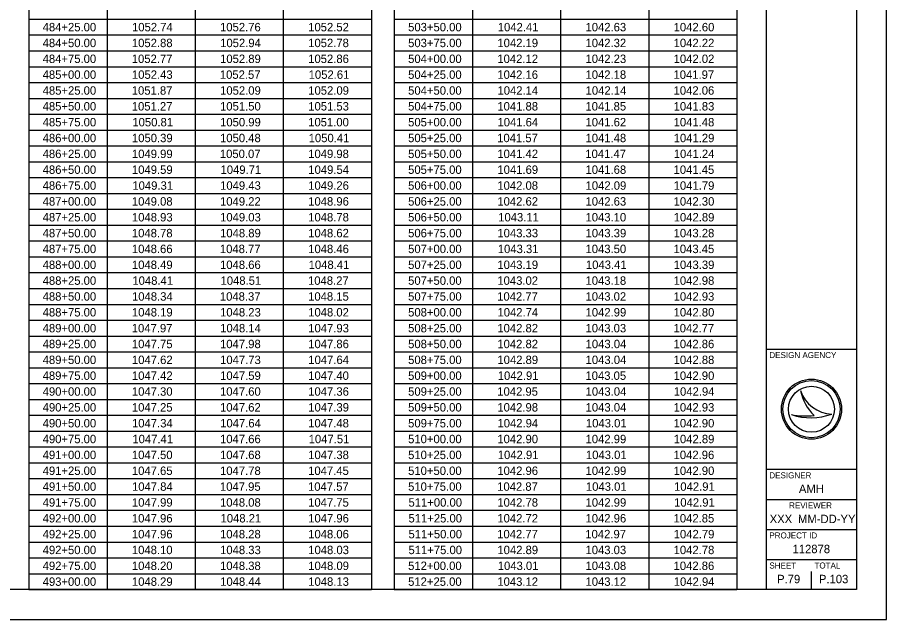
# Model space of a CAD drawing. Extents: x 0 to 34, y 0 to 22.
# Drawn here: x 19.54 to 34, y 0 to 10.02 of the extents above; entities that cross this region are included whole.
import ezdxf

# ---------------------------------------------------------------- set-up
doc = ezdxf.new("R2010")
doc.units = 0
for name, color, linetype in [('SH_Border', 7, 'Continuous'), ('SH_Cut_Line', 7, 'Continuous'), ('SH_Data', 7, 'Continuous'), ('SH_Text', 7, 'Continuous')]:
    doc.layers.add(name, color=color, linetype=linetype)

msp = doc.modelspace()

# ---------------------------------------------------------------- linework, layer by layer
at = {"layer": 'SH_Border'}
for p, q in [((32, 0.5), (32, 21.5)), ((32, 4.5), (33.5, 4.5)), ((32, 2.5), (33.5, 2.5)), ((32, 2), (33.5, 2)), ((32, 1.5), (33.5, 1.5)), ((32, 1), (33.5, 1))]:
    msp.add_line(p, q, dxfattribs=at)
msp.add_lwpolyline([(1.5, 21.5), (33.5, 21.5), (33.5, 0.5), (1.5, 0.5)], close=True, dxfattribs=at)
at = {"layer": 'SH_Cut_Line'}
msp.add_lwpolyline([(0, 0), (34, 0), (34, 22), (0, 22)], close=True, dxfattribs=at)
at = {"layer": 'SH_Data'}
for p, q in [((32.567, 3.81), (32.567, 3.81)), ((32.75, 3.5), (32.75, 3.5)), ((32.417, 3.41), (32.417, 3.41)), ((33.087, 3.419), (33.087, 3.419)), ((32.75, 0.5), (32.75, 0.8)), ((32.375, 0.675), (32.375, 0.675))]:
    msp.add_line(p, q, dxfattribs=at)
for radius in [0.5, 0.477, 0.477, 0.382]:
    msp.add_circle((32.75, 3.5), radius, dxfattribs=at)
for centre, radius, start, end in [((33.116, 3.998), 0.58, 198.9257, 198.9319), ((33.347, 3.97), 0.796, 191.6379, 191.6421), ((33.116, 3.998), 0.58, 198.9319, 267.1657), ((33.347, 3.97), 0.796, 191.6421, 226.0947), ((32.739, 4.37), 1.013, 251.4576, 290.0832), ((32.648, 4.654), 1.266, 259.4964, 259.4995), ((32.739, 4.37), 1.013, 251.4527, 251.4576), ((32.648, 4.654), 1.266, 259.4995, 276.6672)]:
    msp.add_arc(centre, radius, start, end, dxfattribs=at)
at = {"layer": 'SH_Text'}
for p, q in [((19.733, 21.5), (19.733, 0.5)), ((21.034, 21.5), (21.034, 0.5)), ((22.5, 21.5), (22.5, 0.5)), ((23.966, 21.5), (23.966, 0.5)), ((25.432, 21.5), (25.432, 0.5)), ((25.811, 21.5), (25.811, 0.5)), ((27.112, 21.5), (27.112, 0.5)), ((28.578, 21.5), (28.578, 0.5)), ((30.044, 21.5), (30.044, 0.5)), ((31.509, 21.5), (31.509, 0.5)), ((19.733, 9.987), (25.432, 9.987)), ((25.811, 9.987), (31.509, 9.987)), ((19.733, 9.724), (25.432, 9.724)), ((25.811, 9.724), (31.509, 9.724)), ((19.733, 9.46), (25.432, 9.46)), ((25.811, 9.46), (31.509, 9.46)), ((19.733, 9.196), (25.432, 9.196)), ((25.811, 9.196), (31.509, 9.196)), ((19.733, 8.933), (25.432, 8.933)), ((25.811, 8.933), (31.509, 8.933)), ((19.733, 8.669), (25.432, 8.669)), ((25.811, 8.669), (31.509, 8.669)), ((19.733, 8.406), (25.432, 8.406)), ((25.811, 8.406), (31.509, 8.406)), ((19.733, 8.142), (25.432, 8.142)), ((25.811, 8.142), (31.509, 8.142)), ((19.733, 7.879), (25.432, 7.879)), ((25.811, 7.879), (31.509, 7.879)), ((19.733, 7.615), (25.432, 7.615)), ((25.811, 7.615), (31.509, 7.615)), ((19.733, 7.352), (25.432, 7.352)), ((25.811, 7.352), (31.509, 7.352)), ((19.733, 7.088), (25.432, 7.088)), ((25.811, 7.088), (31.509, 7.088)), ((19.733, 6.825), (25.432, 6.825)), ((25.811, 6.825), (31.509, 6.825)), ((19.733, 6.561), (25.432, 6.561)), ((25.811, 6.561), (31.509, 6.561)), ((19.733, 6.298), (25.432, 6.298)), ((25.811, 6.298), (31.509, 6.298)), ((19.733, 6.034), (25.432, 6.034)), ((25.811, 6.034), (31.509, 6.034)), ((19.733, 5.771), (25.432, 5.771)), ((25.811, 5.771), (31.509, 5.771)), ((19.733, 5.507), (25.432, 5.507)), ((25.811, 5.507), (31.509, 5.507)), ((19.733, 5.244), (25.432, 5.244)), ((25.811, 5.244), (31.509, 5.244)), ((19.733, 4.98), (25.432, 4.98)), ((25.811, 4.98), (31.509, 4.98)), ((19.733, 4.716), (25.432, 4.716)), ((25.811, 4.716), (31.509, 4.716)), ((19.733, 4.453), (25.432, 4.453)), ((25.811, 4.453), (31.509, 4.453)), ((19.733, 4.189), (25.432, 4.189)), ((25.811, 4.189), (31.509, 4.189)), ((19.733, 3.926), (25.432, 3.926)), ((25.811, 3.926), (31.509, 3.926)), ((19.733, 3.662), (25.432, 3.662)), ((25.811, 3.662), (31.509, 3.662)), ((19.733, 3.399), (25.432, 3.399)), ((25.811, 3.399), (31.509, 3.399)), ((19.733, 3.135), (25.432, 3.135)), ((25.811, 3.135), (31.509, 3.135)), ((19.733, 2.872), (25.432, 2.872)), ((25.811, 2.872), (31.509, 2.872)), ((19.733, 2.608), (25.432, 2.608)), ((25.811, 2.608), (31.509, 2.608)), ((19.733, 2.345), (25.432, 2.345)), ((25.811, 2.345), (31.509, 2.345)), ((19.733, 2.081), (25.432, 2.081)), ((25.811, 2.081), (31.509, 2.081)), ((19.733, 1.818), (25.432, 1.818)), ((25.811, 1.818), (31.509, 1.818)), ((19.733, 1.554), (25.432, 1.554)), ((25.811, 1.554), (31.509, 1.554)), ((19.733, 1.291), (25.432, 1.291)), ((25.811, 1.291), (31.509, 1.291)), ((19.733, 1.027), (25.432, 1.027)), ((25.811, 1.027), (31.509, 1.027)), ((19.733, 0.764), (25.432, 0.764)), ((25.811, 0.764), (31.509, 0.764)), ((19.733, 0.5), (25.432, 0.5)), ((25.811, 0.5), (31.509, 0.5))]:
    msp.add_line(p, q, dxfattribs=at)

# ---------------------------------------------------------------- texts
at = {"layer": 'SH_Data'}
for s, height, p in [('DESIGN AGENCY', 0.1, (32.05, 4.35)), ('DESIGNER', 0.1, (32.05, 2.35)), ('AMH', 0.14, (32.541, 2.105)), ('REVIEWER', 0.1, (32.378, 1.85)), ('XXX', 0.14, (32.055, 1.605)), ('MM-DD-YY', 0.14, (32.526, 1.605)), ('PROJECT ID', 0.1, (32.05, 1.35)), ('112878', 0.14, (32.435, 1.105)), ('SHEET', 0.1, (32.05, 0.85)), ('TOTAL', 0.1, (32.8, 0.85)), ('P.79', 0.14, (32.178, 0.605)), ('P.103', 0.14, (32.874, 0.605))]:
    msp.add_text(s, height=height, dxfattribs=at).set_placement(p)
at = {"layer": 'SH_Text'}
for s, p in [('484+25.00', (19.964, 9.785)), ('1052.74', (21.45, 9.785)), ('1052.76', (22.914, 9.785)), ('1052.52', (24.38, 9.785)), ('503+50.00', (26.042, 9.785)), ('1042.41', (27.533, 9.785)), ('1042.63', (28.992, 9.785)), ('1042.60', (30.458, 9.785)), ('484+50.00', (19.964, 9.522)), ('1052.88', (21.448, 9.522)), ('1052.94', (22.916, 9.522)), ('1052.78', (24.38, 9.522)), ('503+75.00', (26.042, 9.522)), ('1042.19', (27.527, 9.522)), ('1042.32', (28.992, 9.522)), ('1042.22', (30.458, 9.522)), ('484+75.00', (19.964, 9.258)), ('1052.77', (21.446, 9.258)), ('1052.89', (22.915, 9.258)), ('1052.86', (24.38, 9.258)), ('504+00.00', (26.042, 9.258)), ('1042.12', (27.526, 9.258)), ('1042.23', (28.992, 9.258)), ('1042.02', (30.458, 9.258)), ('485+00.00', (19.964, 8.995)), ('1052.43', (21.449, 8.995)), ('1052.57', (22.911, 8.995)), ('1052.61', (24.388, 8.995)), ('504+25.00', (26.042, 8.995)), ('1042.16', (27.526, 8.995)), ('1042.18', (28.992, 8.995)), ('1041.97', (30.455, 8.995)), ('485+25.00', (19.964, 8.731)), ('1051.87', (21.446, 8.731)), ('1052.09', (22.915, 8.731)), ('1052.09', (24.381, 8.731)), ('504+50.00', (26.042, 8.731)), ('1042.14', (27.528, 8.731)), ('1042.14', (28.994, 8.731)), ('1042.06', (30.457, 8.731)), ('485+50.00', (19.964, 8.468)), ('1051.27', (21.446, 8.468)), ('1051.50', (22.914, 8.468)), ('1051.53', (24.381, 8.468)), ('504+75.00', (26.042, 8.468)), ('1041.88', (27.526, 8.468)), ('1041.85', (28.991, 8.468)), ('1041.83', (30.458, 8.468)), ('485+75.00', (19.964, 8.204)), ('1050.81', (21.456, 8.204)), ('1050.99', (22.915, 8.204)), ('1051.00', (24.38, 8.204)), ('505+00.00', (26.042, 8.204)), ('1041.64', (27.528, 8.204)), ('1041.62', (28.992, 8.204)), ('1041.48', (30.458, 8.204)), ('486+00.00', (19.964, 7.941)), ('1050.39', (21.449, 7.941)), ('1050.48', (22.914, 7.941)), ('1050.41', (24.388, 7.941)), ('505+25.00', (26.042, 7.941)), ('1041.57', (27.523, 7.941)), ('1041.48', (28.992, 7.941)), ('1041.29', (30.459, 7.941)), ('486+25.00', (19.964, 7.677)), ('1049.99', (21.449, 7.677)), ('1050.07', (22.911, 7.677)), ('1049.98', (24.38, 7.677)), ('505+50.00', (26.042, 7.677)), ('1041.42', (27.526, 7.677)), ('1041.47', (28.989, 7.677)), ('1041.24', (30.46, 7.677)), ('486+50.00', (19.964, 7.414)), ('1049.59', (21.449, 7.414)), ('1049.71', (22.922, 7.414)), ('1049.54', (24.382, 7.414)), ('505+75.00', (26.042, 7.414)), ('1041.69', (27.527, 7.414)), ('1041.68', (28.992, 7.414)), ('1041.45', (30.457, 7.414)), ('486+75.00', (19.964, 7.15)), ('1049.31', (21.456, 7.15)), ('1049.43', (22.915, 7.15)), ('1049.26', (24.38, 7.15)), ('506+00.00', (26.042, 7.15)), ('1042.08', (27.526, 7.15)), ('1042.09', (28.993, 7.15)), ('1041.79', (30.459, 7.15)), ('487+00.00', (19.964, 6.886)), ('1049.08', (21.448, 6.886)), ('1049.22', (22.914, 6.886)), ('1048.96', (24.38, 6.886)), ('506+25.00', (26.042, 6.886)), ('1042.62', (27.526, 6.886)), ('1042.63', (28.992, 6.886)), ('1042.30', (30.458, 6.886)), ('487+25.00', (19.964, 6.623)), ('1048.93', (21.449, 6.623)), ('1049.03', (22.915, 6.623)), ('1048.78', (24.38, 6.623)), ('506+50.00', (26.042, 6.623)), ('1043.11', (27.54, 6.623)), ('1043.10', (28.992, 6.623)), ('1042.89', (30.459, 6.623)), ('487+50.00', (19.964, 6.359)), ('1048.78', (21.448, 6.359)), ('1048.89', (22.915, 6.359)), ('1048.62', (24.38, 6.359)), ('506+75.00', (26.042, 6.359)), ('1043.33', (27.527, 6.359)), ('1043.39', (28.993, 6.359)), ('1043.28', (30.458, 6.359)), ('487+75.00', (19.964, 6.096)), ('1048.66', (21.448, 6.096)), ('1048.77', (22.911, 6.096)), ('1048.46', (24.38, 6.096)), ('507+00.00', (26.042, 6.096)), ('1043.31', (27.533, 6.096)), ('1043.50', (28.992, 6.096)), ('1043.45', (30.457, 6.096)), ('488+00.00', (19.964, 5.832)), ('1048.49', (21.449, 5.832)), ('1048.66', (22.914, 5.832)), ('1048.41', (24.388, 5.832)), ('507+25.00', (26.042, 5.832)), ('1043.19', (27.527, 5.832)), ('1043.41', (28.999, 5.832)), ('1043.39', (30.459, 5.832)), ('488+25.00', (19.964, 5.569)), ('1048.41', (21.456, 5.569)), ('1048.51', (22.922, 5.569)), ('1048.27', (24.377, 5.569)), ('507+50.00', (26.042, 5.569)), ('1043.02', (27.526, 5.569)), ('1043.18', (28.992, 5.569)), ('1042.98', (30.458, 5.569)), ('488+50.00', (19.964, 5.305)), ('1048.34', (21.45, 5.305)), ('1048.37', (22.911, 5.305)), ('1048.15', (24.379, 5.305)), ('507+75.00', (26.042, 5.305)), ('1042.77', (27.523, 5.305)), ('1043.02', (28.992, 5.305)), ('1042.93', (30.458, 5.305)), ('488+75.00', (19.964, 5.042)), ('1048.19', (21.449, 5.042)), ('1048.23', (22.915, 5.042)), ('1048.02', (24.38, 5.042)), ('508+00.00', (26.042, 5.042)), ('1042.74', (27.528, 5.042)), ('1042.99', (28.993, 5.042)), ('1042.80', (30.458, 5.042)), ('489+00.00', (19.964, 4.778)), ('1047.97', (21.446, 4.778)), ('1048.14', (22.916, 4.778)), ('1047.93', (24.381, 4.778)), ('508+25.00', (26.042, 4.778)), ('1042.82', (27.526, 4.778)), ('1043.03', (28.992, 4.778)), ('1042.77', (30.455, 4.778)), ('489+25.00', (19.964, 4.515)), ('1047.75', (21.448, 4.515)), ('1047.98', (22.914, 4.515)), ('1047.86', (24.38, 4.515)), ('508+50.00', (26.042, 4.515)), ('1042.82', (27.526, 4.515)), ('1043.04', (28.994, 4.515)), ('1042.86', (30.457, 4.515)), ('489+50.00', (19.964, 4.251)), ('1047.62', (21.449, 4.251)), ('1047.73', (22.915, 4.251)), ('1047.64', (24.382, 4.251)), ('508+75.00', (26.042, 4.251)), ('1042.89', (27.527, 4.251)), ('1043.04', (28.994, 4.251)), ('1042.88', (30.458, 4.251)), ('489+75.00', (19.964, 3.988)), ('1047.42', (21.449, 3.988)), ('1047.59', (22.915, 3.988)), ('1047.40', (24.38, 3.988)), ('509+00.00', (26.042, 3.988)), ('1042.91', (27.533, 3.988)), ('1043.05', (28.991, 3.988)), ('1042.90', (30.458, 3.988)), ('490+00.00', (19.964, 3.724)), ('1047.30', (21.448, 3.724)), ('1047.60', (22.914, 3.724)), ('1047.36', (24.38, 3.724)), ('509+25.00', (26.042, 3.724)), ('1042.95', (27.525, 3.724)), ('1043.04', (28.994, 3.724)), ('1042.94', (30.46, 3.724)), ('490+25.00', (19.964, 3.461)), ('1047.25', (21.448, 3.461)), ('1047.62', (22.914, 3.461)), ('1047.39', (24.381, 3.461)), ('509+50.00', (26.042, 3.461)), ('1042.98', (27.526, 3.461)), ('1043.04', (28.994, 3.461)), ('1042.93', (30.458, 3.461)), ('490+50.00', (19.964, 3.197)), ('1047.34', (21.45, 3.197)), ('1047.64', (22.916, 3.197)), ('1047.48', (24.38, 3.197)), ('509+75.00', (26.042, 3.197)), ('1042.94', (27.528, 3.197)), ('1043.01', (28.999, 3.197)), ('1042.90', (30.458, 3.197)), ('490+75.00', (19.964, 2.934)), ('1047.41', (21.456, 2.934)), ('1047.66', (22.914, 2.934)), ('1047.51', (24.388, 2.934)), ('510+00.00', (26.042, 2.934)), ('1042.90', (27.526, 2.934)), ('1042.99', (28.993, 2.934)), ('1042.89', (30.459, 2.934)), ('491+00.00', (19.964, 2.67)), ('1047.50', (21.448, 2.67)), ('1047.68', (22.914, 2.67)), ('1047.38', (24.38, 2.67)), ('510+25.00', (26.042, 2.67)), ('1042.91', (27.533, 2.67)), ('1043.01', (28.999, 2.67)), ('1042.96', (30.457, 2.67)), ('491+25.00', (19.964, 2.406)), ('1047.65', (21.448, 2.406)), ('1047.78', (22.914, 2.406)), ('1047.45', (24.379, 2.406)), ('510+50.00', (26.042, 2.406)), ('1042.96', (27.526, 2.406)), ('1042.99', (28.993, 2.406)), ('1042.90', (30.458, 2.406)), ('491+50.00', (19.964, 2.143)), ('1047.84', (21.45, 2.143)), ('1047.95', (22.913, 2.143)), ('1047.57', (24.377, 2.143)), ('510+75.00', (26.042, 2.143)), ('1042.87', (27.523, 2.143)), ('1043.01', (28.999, 2.143)), ('1042.91', (30.465, 2.143)), ('491+75.00', (19.964, 1.879)), ('1047.99', (21.449, 1.879)), ('1048.08', (22.914, 1.879)), ('1047.75', (24.379, 1.879)), ('511+00.00', (26.048, 1.879)), ('1042.78', (27.526, 1.879)), ('1042.99', (28.993, 1.879)), ('1042.91', (30.465, 1.879)), ('492+00.00', (19.964, 1.616)), ('1047.96', (21.448, 1.616)), ('1048.21', (22.922, 1.616)), ('1047.96', (24.38, 1.616)), ('511+25.00', (26.048, 1.616)), ('1042.72', (27.526, 1.616)), ('1042.96', (28.992, 1.616)), ('1042.85', (30.457, 1.616)), ('492+25.00', (19.964, 1.352)), ('1047.96', (21.448, 1.352)), ('1048.28', (22.914, 1.352)), ('1048.06', (24.38, 1.352)), ('511+50.00', (26.048, 1.352)), ('1042.77', (27.523, 1.352)), ('1042.97', (28.989, 1.352)), ('1042.79', (30.459, 1.352)), ('492+50.00', (19.964, 1.089)), ('1048.10', (21.448, 1.089)), ('1048.33', (22.915, 1.089)), ('1048.03', (24.381, 1.089)), ('511+75.00', (26.048, 1.089)), ('1042.89', (27.527, 1.089)), ('1043.03', (28.992, 1.089)), ('1042.78', (30.458, 1.089)), ('492+75.00', (19.964, 0.825)), ('1048.20', (21.448, 0.825)), ('1048.38', (22.914, 0.825)), ('1048.09', (24.381, 0.825)), ('512+00.00', (26.042, 0.825)), ('1043.01', (27.533, 0.825)), ('1043.08', (28.992, 0.825)), ('1042.86', (30.457, 0.825)), ('493+00.00', (19.964, 0.562)), ('1048.29', (21.449, 0.562)), ('1048.44', (22.916, 0.562)), ('1048.13', (24.381, 0.562)), ('512+25.00', (26.042, 0.562)), ('1043.12', (27.526, 0.562)), ('1043.12', (28.992, 0.562)), ('1042.94', (30.46, 0.562))]:
    msp.add_text(s, height=0.14, dxfattribs=at).set_placement(p)

doc.saveas('drawing.dxf')
